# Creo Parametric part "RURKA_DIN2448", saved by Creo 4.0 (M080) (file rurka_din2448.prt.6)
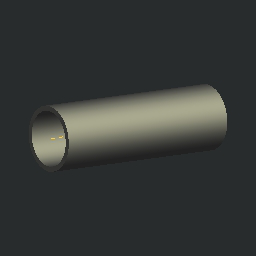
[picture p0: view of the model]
Units: Custom; MM, KILOGRAM, SECS
Materials in the file: OCEL_N

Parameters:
  V_T = "2"
  N_T = "6"
  B_T = "2.6"
  QUERSCHNITT_QCM = "2.54"
  W_CCM = "1.84"
  KATEGORIE = "0"
  DESIGNER = "."
  DATE = "."
  FORMAT = "."
  X_T = "33"
  Y_T = "7"
  Z_T = "33.7"
  NAZOV = "RURKA_DIN2448"
  ROZMER = "Tr 33.7x2.6x100 STN ...."
  HMOTNOST_HR = "."
  MATERIAL_ZAKL = "."
  NORMA = "DIN 2448"
  PTC_MATERIAL_NAME = "OCEL_N"

Other parameters: L, D, T, HMOTNOST, HUSTOTA, HMOTNOST_1, D26, D27

Created from: TRUBKA.PRT

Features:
  1. datum plane "Y-Y"
  2. datum plane "X-X"
  3. datum plane "Z-Z"
  4. coordinate system
  5. datum axis
  6. datum axis
  7. datum axis
  8. protrusion
  9. curve

Other named items: ZZ, YY, XX, CS0

Named dimensions: Durchmesser, Dicke, Laenge, laenge_nf

Layers: BEZUG, BEZUGSACHSEN, PLAZIERUNG, PROFIL_NEUTRALE_FASER

Notes: Hohlprofil | DxTxL 34x2.6x100 | Gewicht:  | 0.590 | Widerstandsmoment-W:  | 1.84 |  cm³ | Querschnittsflaeche-A:  | 2.54 |  cm²

Family table entries: GENERIC, RURKA_33_7X2_6, RURKA_DIN2448, value(d_val), value(s_val), 2.54, 31.84, value(i_val), RURKA_33_7X3_2, RURKA_DIN2448, "3.07, 32.14, RURKA_33_7X4, RURKA_DIN2448, "3.73, 32.49, RURKA_42_4X2_6, RURKA_DIN2448, "3.25, 33.05, RURKA_42_4X3_2, RURKA_DIN2448, "3.94, 33.59, RURKA_42_4X4, RURKA_DIN2448, "4.83, 34.24, RURKA_48_3X2_6, RURKA_DIN2448, "3.73, 34.05, RURKA_48_3X3_2, RURKA_DIN2448, "4.63, 34.80, RURKA_48_3X4, RURKA_DIN2448, "5.57, 35.70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

Surfaces: 2 plane, 2 cylinder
